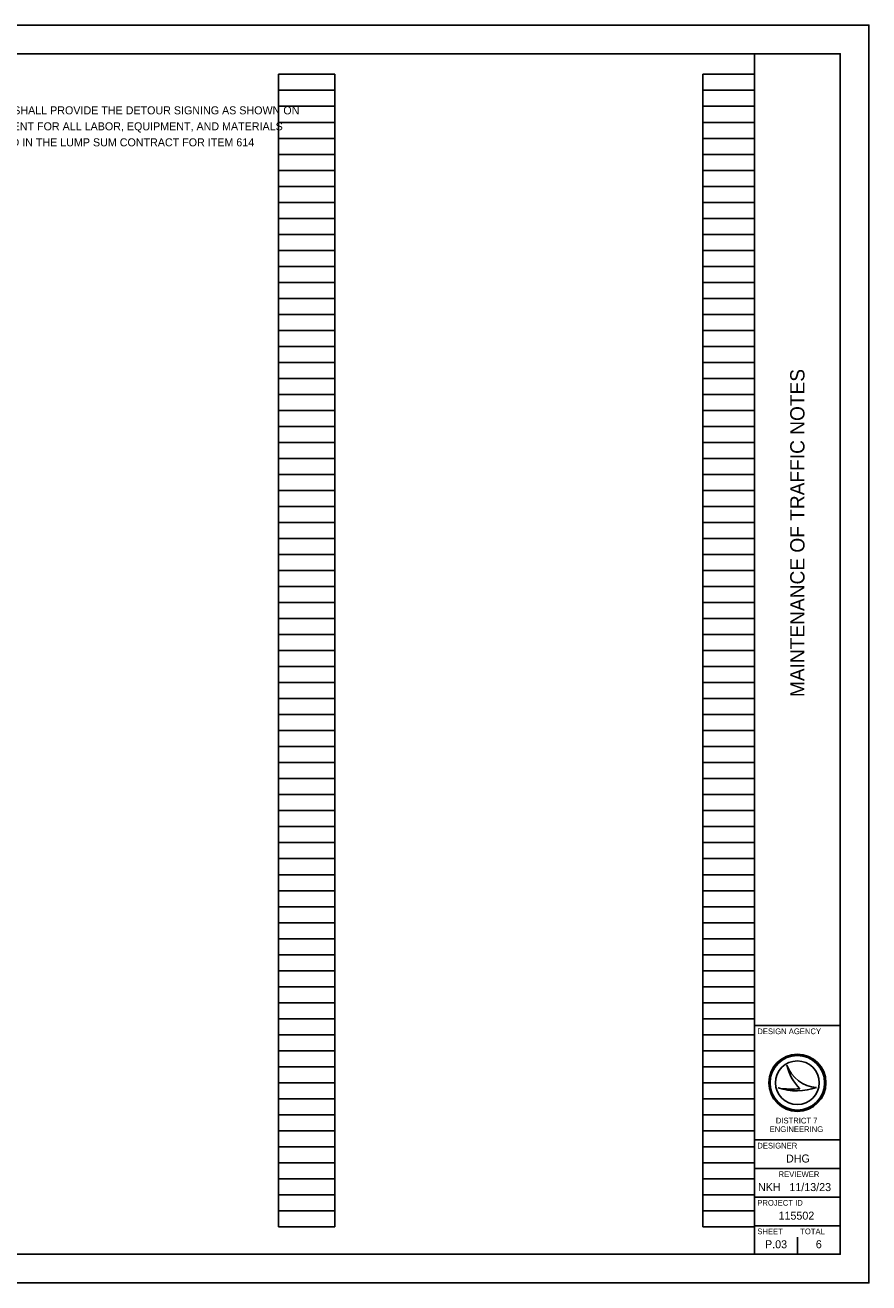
# Model space of a CAD drawing. Extents: x 0 to 34, y 0 to 22.
# Drawn here: x 19.25 to 34, y 0 to 22 of the extents above; entities that cross this region are included whole.
import ezdxf

# ---------------------------------------------------------------- set-up
doc = ezdxf.new("R2010")
doc.units = 0
for name, color, linetype in [('SC_Scratch1', 7, 'Continuous'), ('SH_Border', 7, 'Continuous'), ('SH_Cut_Line', 7, 'Continuous'), ('SH_Data', 7, 'Continuous'), ('SH_Text', 7, 'Continuous')]:
    doc.layers.add(name, color=color, linetype=linetype)

msp = doc.modelspace()

# ---------------------------------------------------------------- linework, layer by layer
at = {"layer": 'SC_Scratch1'}
for p, q in [((23.68, 0.98), (23.68, 21.14)), ((23.68, 21.14), (24.66, 21.14)), ((24.66, 0.98), (24.66, 21.14)), ((31.1, 0.98), (31.1, 21.14)), ((31.1, 21.14), (32, 21.14)), ((32, 0.98), (32, 21.14)), ((23.68, 20.86), (24.66, 20.86)), ((31.1, 20.86), (32, 20.86)), ((23.68, 20.58), (24.66, 20.58)), ((31.1, 20.58), (32, 20.58)), ((23.68, 20.3), (24.66, 20.3)), ((31.1, 20.3), (32, 20.3)), ((23.68, 20.02), (24.66, 20.02)), ((31.1, 20.02), (32, 20.02)), ((23.68, 19.74), (24.66, 19.74)), ((31.1, 19.74), (32, 19.74)), ((23.68, 19.46), (24.66, 19.46)), ((31.1, 19.46), (32, 19.46)), ((23.68, 19.18), (24.66, 19.18)), ((31.1, 19.18), (32, 19.18)), ((23.68, 18.9), (24.66, 18.9)), ((31.1, 18.9), (32, 18.9)), ((23.68, 18.62), (24.66, 18.62)), ((31.1, 18.62), (32, 18.62)), ((23.68, 18.34), (24.66, 18.34)), ((31.1, 18.34), (32, 18.34)), ((23.68, 18.06), (24.66, 18.06)), ((31.1, 18.06), (32, 18.06)), ((23.68, 17.78), (24.66, 17.78)), ((31.1, 17.78), (32, 17.78)), ((23.68, 17.5), (24.66, 17.5)), ((31.1, 17.5), (32, 17.5)), ((23.68, 17.22), (24.66, 17.22)), ((31.1, 17.22), (32, 17.22)), ((23.68, 16.94), (24.66, 16.94)), ((31.1, 16.94), (32, 16.94)), ((23.68, 16.66), (24.66, 16.66)), ((31.1, 16.66), (32, 16.66)), ((23.68, 16.38), (24.66, 16.38)), ((31.1, 16.38), (32, 16.38)), ((23.68, 16.1), (24.66, 16.1)), ((31.1, 16.1), (32, 16.1)), ((23.68, 15.82), (24.66, 15.82)), ((31.1, 15.82), (32, 15.82)), ((23.68, 15.54), (24.66, 15.54)), ((31.1, 15.54), (32, 15.54)), ((23.68, 15.26), (24.66, 15.26)), ((31.1, 15.26), (32, 15.26)), ((23.68, 14.98), (24.66, 14.98)), ((31.1, 14.98), (32, 14.98)), ((23.68, 14.7), (24.66, 14.7)), ((31.1, 14.7), (32, 14.7)), ((23.68, 14.42), (24.66, 14.42)), ((31.1, 14.42), (32, 14.42)), ((23.68, 14.14), (24.66, 14.14)), ((31.1, 14.14), (32, 14.14)), ((23.68, 13.86), (24.66, 13.86)), ((31.1, 13.86), (32, 13.86)), ((23.68, 13.58), (24.66, 13.58)), ((31.1, 13.58), (32, 13.58)), ((23.68, 13.3), (24.66, 13.3)), ((31.1, 13.3), (32, 13.3)), ((23.68, 13.02), (24.66, 13.02)), ((31.1, 13.02), (32, 13.02)), ((23.68, 12.74), (24.66, 12.74)), ((31.1, 12.74), (32, 12.74)), ((23.68, 12.46), (24.66, 12.46)), ((31.1, 12.46), (32, 12.46)), ((23.68, 12.18), (24.66, 12.18)), ((31.1, 12.18), (32, 12.18)), ((23.68, 11.9), (24.66, 11.9)), ((31.1, 11.9), (32, 11.9)), ((23.68, 11.62), (24.66, 11.62)), ((31.1, 11.62), (32, 11.62)), ((23.68, 11.34), (24.66, 11.34)), ((31.1, 11.34), (32, 11.34)), ((23.68, 11.06), (24.66, 11.06)), ((31.1, 11.06), (32, 11.06)), ((23.68, 10.78), (24.66, 10.78)), ((31.1, 10.78), (32, 10.78)), ((23.68, 10.5), (24.66, 10.5)), ((31.1, 10.5), (32, 10.5)), ((23.68, 10.22), (24.66, 10.22)), ((31.1, 10.22), (32, 10.22)), ((23.68, 9.94), (24.66, 9.94)), ((31.1, 9.94), (32, 9.94)), ((23.68, 9.66), (24.66, 9.66)), ((31.1, 9.66), (32, 9.66)), ((23.68, 9.38), (24.66, 9.38)), ((31.1, 9.38), (32, 9.38)), ((23.68, 9.1), (24.66, 9.1)), ((31.1, 9.1), (32, 9.1)), ((23.68, 8.82), (24.66, 8.82)), ((31.1, 8.82), (32, 8.82)), ((23.68, 8.54), (24.66, 8.54)), ((31.1, 8.54), (32, 8.54)), ((23.68, 8.26), (24.66, 8.26)), ((31.1, 8.26), (32, 8.26)), ((23.68, 7.98), (24.66, 7.98)), ((31.1, 7.98), (32, 7.98)), ((23.68, 7.7), (24.66, 7.7)), ((31.1, 7.7), (32, 7.7)), ((23.68, 7.42), (24.66, 7.42)), ((31.1, 7.42), (32, 7.42)), ((23.68, 7.14), (24.66, 7.14)), ((31.1, 7.14), (32, 7.14)), ((23.68, 6.86), (24.66, 6.86)), ((31.1, 6.86), (32, 6.86)), ((23.68, 6.58), (24.66, 6.58)), ((31.1, 6.58), (32, 6.58)), ((23.68, 6.3), (24.66, 6.3)), ((31.1, 6.3), (32, 6.3)), ((23.68, 6.02), (24.66, 6.02)), ((31.1, 6.02), (32, 6.02)), ((23.68, 5.74), (24.66, 5.74)), ((31.1, 5.74), (32, 5.74)), ((23.68, 5.46), (24.66, 5.46)), ((31.1, 5.46), (32, 5.46)), ((23.68, 5.18), (24.66, 5.18)), ((31.1, 5.18), (32, 5.18)), ((23.68, 4.9), (24.66, 4.9)), ((31.1, 4.9), (32, 4.9)), ((23.68, 4.62), (24.66, 4.62)), ((31.1, 4.62), (32, 4.62)), ((23.68, 4.34), (24.66, 4.34)), ((31.1, 4.34), (32, 4.34)), ((23.68, 4.06), (24.66, 4.06)), ((31.1, 4.06), (32, 4.06)), ((23.68, 3.78), (24.66, 3.78)), ((31.1, 3.78), (32, 3.78)), ((23.68, 3.5), (24.66, 3.5)), ((31.1, 3.5), (32, 3.5)), ((23.68, 3.22), (24.66, 3.22)), ((31.1, 3.22), (32, 3.22)), ((23.68, 2.94), (24.66, 2.94)), ((31.1, 2.94), (32, 2.94)), ((23.68, 2.66), (24.66, 2.66)), ((31.1, 2.66), (32, 2.66)), ((23.68, 2.38), (24.66, 2.38)), ((31.1, 2.38), (32, 2.38)), ((23.68, 2.1), (24.66, 2.1)), ((31.1, 2.1), (32, 2.1)), ((23.68, 1.82), (24.66, 1.82)), ((31.1, 1.82), (32, 1.82)), ((23.68, 1.54), (24.66, 1.54)), ((31.1, 1.54), (32, 1.54)), ((23.68, 1.26), (24.66, 1.26)), ((31.1, 1.26), (32, 1.26)), ((23.68, 0.98), (24.66, 0.98)), ((31.1, 0.98), (32, 0.98))]:
    msp.add_line(p, q, dxfattribs=at)
at = {"layer": 'SH_Border'}
for p, q in [((32, 0.5), (32, 21.5)), ((32, 4.5), (33.5, 4.5)), ((32, 2.5), (33.5, 2.5)), ((32, 2), (33.5, 2)), ((32, 1.5), (33.5, 1.5)), ((32, 1), (33.5, 1))]:
    msp.add_line(p, q, dxfattribs=at)
msp.add_lwpolyline([(1.5, 21.5), (33.5, 21.5), (33.5, 0.5), (1.5, 0.5)], close=True, dxfattribs=at)
at = {"layer": 'SH_Cut_Line'}
msp.add_lwpolyline([(0, 0), (34, 0), (34, 22), (0, 22)], close=True, dxfattribs=at)
at = {"layer": 'SH_Data'}
for p, q in [((32.567, 3.81), (32.567, 3.81)), ((32.417, 3.41), (32.417, 3.41)), ((32.75, 3.5), (32.75, 3.5)), ((33.087, 3.419), (33.087, 3.419)), ((32.375, 0.675), (32.375, 0.675)), ((32.75, 0.5), (32.75, 0.8))]:
    msp.add_line(p, q, dxfattribs=at)
for radius in [0.5, 0.477, 0.477, 0.382]:
    msp.add_circle((32.75, 3.5), radius, dxfattribs=at)
for centre, radius, start, end in [((33.116, 3.998), 0.58, 198.9257, 198.9319), ((33.347, 3.97), 0.796, 191.6379, 191.6421), ((33.116, 3.998), 0.58, 198.9319, 267.1657), ((33.347, 3.97), 0.796, 191.6421, 226.0947), ((32.739, 4.37), 1.013, 251.4576, 290.0832), ((32.648, 4.654), 1.266, 259.4964, 259.4995), ((32.739, 4.37), 1.013, 251.4527, 251.4576), ((32.648, 4.654), 1.266, 259.4995, 276.6672)]:
    msp.add_arc(centre, radius, start, end, dxfattribs=at)

# ---------------------------------------------------------------- texts
msp.add_text('MAINTENANCE OF TRAFFIC NOTES', height=0.25, rotation=90, dxfattribs=at).set_placement((32.875, 10.247))
for s, height, p in [('DESIGN AGENCY', 0.1, (32.05, 4.35)), ('DESIGNER', 0.1, (32.05, 2.35)), ('DHG', 0.14, (32.552, 2.105)), ('REVIEWER', 0.1, (32.422, 1.85)), ('NKH', 0.14, (32.062, 1.605)), ('11/13/23', 0.14, (32.611, 1.605)), ('PROJECT ID', 0.1, (32.05, 1.35)), ('115502', 0.14, (32.421, 1.105)), ('SHEET', 0.1, (32.05, 0.85)), ('TOTAL', 0.1, (32.8, 0.85)), ('P.03', 0.14, (32.185, 0.605)), ('6', 0.14, (33.073, 0.605))]:
    msp.add_text(s, height=height, dxfattribs=at).set_placement(p)
at = {"layer": 'SH_Text'}
for s, height, p in [('THE CONTRACTOR SHALL PROVIDE THE DETOUR SIGNING AS SHOWN ON', 0.14, (17.24, 20.44)), ('THIS SHEET.  PAYMENT FOR ALL LABOR, EQUIPMENT, AND MATERIALS', 0.14, (17.24, 20.16)), ('SHALL BE INCLUDED IN THE LUMP SUM CONTRACT FOR ITEM 614', 0.14, (17.24, 19.88)), ('DISTRICT 7', 0.1, (32.374, 2.788)), ('ENGINEERING', 0.1, (32.265, 2.638))]:
    msp.add_text(s, height=height, dxfattribs=at).set_placement(p)

doc.saveas('drawing.dxf')
